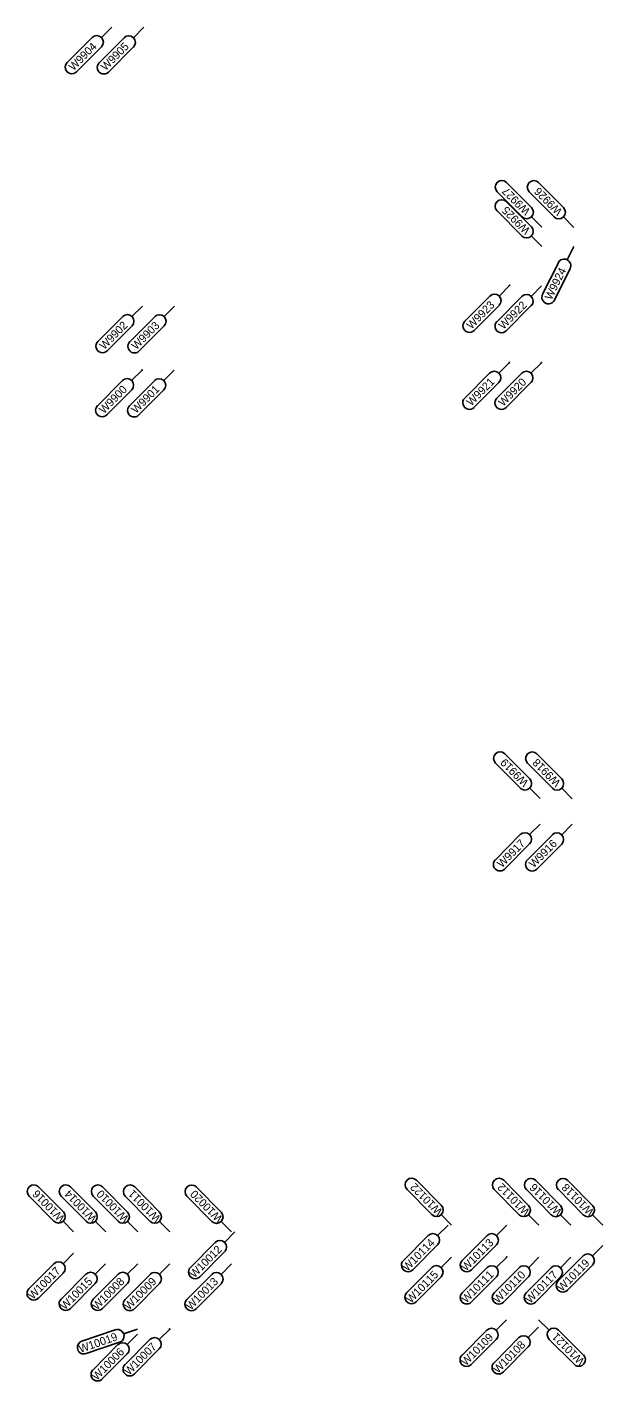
# Model space of a CAD drawing. Extents: x 12479652 to 12487250, y 9842710 to 9846560.
# Drawn here: x 12483661.3 to 12483751.2, y 9844931.3 to 9845142.7 of the extents above; entities that cross this region are included whole.
import ezdxf

# ---------------------------------------------------------------- set-up
doc = ezdxf.new("R2010")
doc.units = 0
doc.layers.add('Default', color=7, linetype='Continuous')
doc.layers.add('TextAlignmentLrg', color=7, linetype='Continuous')

msp = doc.modelspace()

# ---------------------------------------------------------------- linework, layer by layer
at = {"layer": 'Default'}
for p, q in [((12483674.53, 9845142.71), (12483672.91, 9845141.08)), ((12483679.53, 9845142.68), (12483677.91, 9845141.05)), ((12483667.57, 9845137.16), (12483671.46, 9845141.07)), ((12483672.57, 9845137.13), (12483676.46, 9845141.05)), ((12483672.91, 9845139.63), (12483669.02, 9845135.71)), ((12483677.91, 9845139.6), (12483674.02, 9845135.69)), ((12483740.01, 9845114.53), (12483736.12, 9845118.44)), ((12483745.01, 9845114.51), (12483741.12, 9845118.43)), ((12483734.66, 9845116.99), (12483738.55, 9845113.08)), ((12483740, 9845111.53), (12483736.11, 9845115.44)), ((12483739.66, 9845116.98), (12483743.55, 9845113.07)), ((12483734.65, 9845113.99), (12483738.54, 9845110.08)), ((12483741.62, 9845111.45), (12483740, 9845113.08)), ((12483746.62, 9845111.43), (12483745, 9845113.06)), ((12483741.62, 9845108.45), (12483739.99, 9845110.08)), ((12483746.62, 9845108.43), (12483745.59, 9845106.37)), ((12483741.76, 9845100.97), (12483744.22, 9845105.91)), ((12483746.05, 9845104.99), (12483743.6, 9845100.06)), ((12483736.6, 9845102.33), (12483734.98, 9845100.7)), ((12483741.6, 9845102.28), (12483739.98, 9845100.65)), ((12483729.64, 9845096.79), (12483733.53, 9845100.7)), ((12483734.64, 9845096.73), (12483738.52, 9845100.65)), ((12483679.31, 9845099.13), (12483677.69, 9845097.5)), ((12483684.31, 9845099.12), (12483682.69, 9845097.49)), ((12483734.98, 9845099.25), (12483731.09, 9845095.34)), ((12483739.98, 9845099.2), (12483736.09, 9845095.29)), ((12483672.35, 9845093.58), (12483676.24, 9845097.49)), ((12483677.7, 9845096.05), (12483673.81, 9845092.13)), ((12483677.35, 9845093.57), (12483681.24, 9845097.48)), ((12483682.7, 9845096.04), (12483678.81, 9845092.13)), ((12483736.56, 9845090.29), (12483734.94, 9845088.66)), ((12483741.56, 9845090.28), (12483739.94, 9845088.65)), ((12483672.3, 9845083.58), (12483676.19, 9845087.49)), ((12483677.3, 9845083.57), (12483681.19, 9845087.48)), ((12483679.26, 9845089.13), (12483677.64, 9845087.5)), ((12483684.26, 9845089.12), (12483682.64, 9845087.49)), ((12483729.6, 9845084.74), (12483733.49, 9845088.65)), ((12483734.6, 9845084.73), (12483738.49, 9845088.65)), ((12483677.65, 9845086.05), (12483673.76, 9845082.13)), ((12483682.65, 9845086.04), (12483678.76, 9845082.13)), ((12483734.94, 9845087.21), (12483731.05, 9845083.29)), ((12483739.94, 9845087.2), (12483736.05, 9845083.29)), ((12483739.74, 9845025.3), (12483735.85, 9845029.21)), ((12483744.74, 9845025.28), (12483740.85, 9845029.2)), ((12483734.4, 9845027.76), (12483738.29, 9845023.85)), ((12483739.4, 9845027.75), (12483743.29, 9845023.84)), ((12483741.36, 9845022.21), (12483739.74, 9845023.85)), ((12483746.36, 9845022.2), (12483744.74, 9845023.83)), ((12483741.35, 9845018.21), (12483739.73, 9845016.58)), ((12483746.35, 9845018.2), (12483744.73, 9845016.57)), ((12483734.39, 9845012.67), (12483738.28, 9845016.58)), ((12483739.39, 9845012.65), (12483743.28, 9845016.56)), ((12483739.73, 9845015.13), (12483735.84, 9845011.22)), ((12483744.73, 9845015.12), (12483740.84, 9845011.2)), ((12483666.98, 9844957.66), (12483663.11, 9844961.58)), ((12483671.98, 9844957.65), (12483668.11, 9844961.58)), ((12483676.98, 9844957.64), (12483673.11, 9844961.57)), ((12483681.98, 9844957.64), (12483678.11, 9844961.56)), ((12483691.61, 9844957.62), (12483687.73, 9844961.55)), ((12483720.61, 9844961.18), (12483724.49, 9844957.25)), ((12483725.95, 9844958.69), (12483722.07, 9844962.62)), ((12483734.22, 9844961.16), (12483738.09, 9844957.23)), ((12483739.55, 9844958.67), (12483735.68, 9844962.6)), ((12483739.22, 9844961.15), (12483743.09, 9844957.22)), ((12483744.55, 9844958.67), (12483740.68, 9844962.59)), ((12483744.22, 9844961.14), (12483748.09, 9844957.22)), ((12483749.55, 9844958.66), (12483745.68, 9844962.58)), ((12483661.65, 9844960.14), (12483665.52, 9844956.22)), ((12483666.65, 9844960.13), (12483670.52, 9844956.21)), ((12483671.65, 9844960.13), (12483675.52, 9844956.2)), ((12483676.65, 9844960.12), (12483680.53, 9844956.19)), ((12483686.27, 9844960.1), (12483690.15, 9844956.18)), ((12483727.55, 9844955.61), (12483725.94, 9844957.24)), ((12483741.16, 9844955.59), (12483739.54, 9844957.22)), ((12483746.16, 9844955.58), (12483744.54, 9844957.21)), ((12483751.16, 9844955.57), (12483749.54, 9844957.21)), ((12483668.59, 9844954.57), (12483666.97, 9844956.21)), ((12483673.59, 9844954.56), (12483671.97, 9844956.2)), ((12483678.59, 9844954.56), (12483676.97, 9844956.19)), ((12483683.59, 9844954.55), (12483681.98, 9844956.19)), ((12483693.22, 9844954.53), (12483691.6, 9844956.17)), ((12483693.76, 9844954.53), (12483692.14, 9844952.9)), ((12483727, 9844955.61), (12483725.37, 9844953.98)), ((12483736.16, 9844955.6), (12483734.54, 9844953.97)), ((12483686.8, 9844948.99), (12483690.69, 9844952.9)), ((12483720.03, 9844950.06), (12483723.92, 9844953.97)), ((12483725.38, 9844952.53), (12483721.49, 9844948.61)), ((12483729.2, 9844950.05), (12483733.09, 9844953.97)), ((12483734.54, 9844952.52), (12483730.65, 9844948.61)), ((12483751.16, 9844952.43), (12483749.54, 9844950.8)), ((12483668.59, 9844951.2), (12483666.96, 9844949.56)), ((12483692.14, 9844951.45), (12483688.25, 9844947.54)), ((12483727.55, 9844950.61), (12483725.92, 9844948.98)), ((12483736.15, 9844950.59), (12483734.53, 9844948.96)), ((12483741.15, 9844950.59), (12483739.53, 9844948.95)), ((12483744.19, 9844946.88), (12483748.08, 9844950.79)), ((12483746.15, 9844950.58), (12483744.53, 9844948.95)), ((12483661.62, 9844945.65), (12483665.51, 9844949.56)), ((12483666.97, 9844948.11), (12483663.08, 9844944.2)), ((12483666.62, 9844944.02), (12483670.51, 9844947.93)), ((12483671.62, 9844944.01), (12483675.51, 9844947.92)), ((12483673.58, 9844949.56), (12483671.96, 9844947.93)), ((12483676.62, 9844944), (12483680.51, 9844947.91)), ((12483678.58, 9844949.56), (12483676.96, 9844947.93)), ((12483683.58, 9844949.55), (12483681.96, 9844947.92)), ((12483693.21, 9844949.53), (12483691.59, 9844947.9)), ((12483720.58, 9844945.06), (12483724.47, 9844948.97)), ((12483729.19, 9844945.05), (12483733.08, 9844948.96)), ((12483734.19, 9844945.04), (12483738.08, 9844948.95)), ((12483739.19, 9844945.03), (12483743.08, 9844948.94)), ((12483749.54, 9844949.34), (12483745.65, 9844945.43)), ((12483671.97, 9844946.48), (12483668.08, 9844942.57)), ((12483676.97, 9844946.47), (12483673.08, 9844942.56)), ((12483681.97, 9844946.47), (12483678.08, 9844942.55)), ((12483686.25, 9844943.99), (12483690.14, 9844947.9)), ((12483691.59, 9844946.45), (12483687.7, 9844942.54)), ((12483725.93, 9844947.52), (12483722.04, 9844943.61)), ((12483734.54, 9844947.51), (12483730.65, 9844943.6)), ((12483739.54, 9844947.5), (12483735.65, 9844943.59)), ((12483744.54, 9844947.5), (12483740.65, 9844943.58)), ((12483736.14, 9844940.83), (12483734.52, 9844939.2)), ((12483741.14, 9844939.66), (12483739.52, 9844938.03)), ((12483741.14, 9844940.82), (12483742.77, 9844939.2)), ((12483669.87, 9844937.47), (12483675.09, 9844939.26)), ((12483678.57, 9844939.36), (12483676.39, 9844938.62)), ((12483676.61, 9844933.81), (12483680.5, 9844937.72)), ((12483678.57, 9844938.56), (12483676.95, 9844936.93)), ((12483683.57, 9844939.35), (12483681.95, 9844937.72)), ((12483729.18, 9844935.28), (12483733.07, 9844939.19)), ((12483734.52, 9844937.75), (12483730.63, 9844933.83)), ((12483734.18, 9844934.11), (12483738.06, 9844938.03)), ((12483746.69, 9844933.86), (12483742.77, 9844937.75)), ((12483744.22, 9844939.2), (12483748.13, 9844935.31)), ((12483675.75, 9844937.31), (12483670.53, 9844935.53)), ((12483671.61, 9844933.02), (12483675.49, 9844936.93)), ((12483676.95, 9844935.48), (12483673.06, 9844931.57)), ((12483681.95, 9844936.27), (12483678.06, 9844932.36)), ((12483739.52, 9844936.58), (12483735.63, 9844932.67))]:
    msp.add_line(p, q, dxfattribs=at)
for centre, start, end in [((12483672.19, 9845140.35), 315.1702, 135.1702), ((12483677.19, 9845140.32), 315.1702, 135.1702), ((12483668.3, 9845136.44), 135.1702, 315.1702), ((12483673.3, 9845136.41), 135.1702, 315.1702), ((12483735.39, 9845117.72), 44.8253, 224.8253), ((12483740.39, 9845117.7), 44.8253, 224.8253), ((12483735.38, 9845114.72), 44.8253, 224.8253), ((12483739.28, 9845113.8), 224.8253, 44.8253), ((12483744.28, 9845113.79), 224.8253, 44.8253), ((12483739.27, 9845110.8), 224.8253, 44.8253), ((12483745.13, 9845105.45), 333.5553, 153.5553), ((12483734.25, 9845099.98), 315.1702, 135.1702), ((12483739.25, 9845099.92), 315.1702, 135.1702), ((12483742.68, 9845100.51), 153.5553, 333.5553), ((12483676.97, 9845096.77), 315.1702, 135.1702), ((12483681.97, 9845096.76), 315.1702, 135.1702), ((12483730.36, 9845096.06), 135.1702, 315.1702), ((12483735.36, 9845096.01), 135.1702, 315.1702), ((12483673.08, 9845092.86), 135.1702, 315.1702), ((12483678.08, 9845092.85), 135.1702, 315.1702), ((12483676.92, 9845086.77), 315.1702, 135.1702), ((12483681.92, 9845086.76), 315.1702, 135.1702), ((12483734.22, 9845087.93), 315.1702, 135.1702), ((12483739.22, 9845087.92), 315.1702, 135.1702), ((12483673.03, 9845082.86), 135.1702, 315.1702), ((12483678.03, 9845082.85), 135.1702, 315.1702), ((12483730.33, 9845084.02), 135.1702, 315.1702), ((12483735.33, 9845084.01), 135.1702, 315.1702), ((12483735.13, 9845028.49), 44.8253, 224.8253), ((12483740.13, 9845028.47), 44.8253, 224.8253), ((12483739.01, 9845024.57), 224.8253, 44.8253), ((12483744.01, 9845024.56), 224.8253, 44.8253), ((12483739, 9845015.86), 315.1702, 135.1702), ((12483744, 9845015.84), 315.1702, 135.1702), ((12483735.11, 9845011.94), 135.1702, 315.1702), ((12483740.11, 9845011.93), 135.1702, 315.1702), ((12483721.34, 9844961.9), 44.6553, 224.6553), ((12483734.95, 9844961.88), 44.6553, 224.6553), ((12483739.95, 9844961.87), 44.6553, 224.6553), ((12483744.95, 9844961.86), 44.6553, 224.6553), ((12483662.38, 9844960.86), 44.6553, 224.6553), ((12483667.38, 9844960.86), 44.6553, 224.6553), ((12483672.38, 9844960.85), 44.6553, 224.6553), ((12483677.38, 9844960.84), 44.6553, 224.6553), ((12483687, 9844960.83), 44.6553, 224.6553), ((12483725.22, 9844957.97), 224.6553, 44.6553), ((12483738.82, 9844957.95), 224.6553, 44.6553), ((12483743.82, 9844957.94), 224.6553, 44.6553), ((12483748.82, 9844957.94), 224.6553, 44.6553), ((12483666.25, 9844956.94), 224.6553, 44.6553), ((12483671.25, 9844956.93), 224.6553, 44.6553), ((12483676.25, 9844956.92), 224.6553, 44.6553), ((12483681.25, 9844956.92), 224.6553, 44.6553), ((12483690.88, 9844956.9), 224.6553, 44.6553), ((12483724.65, 9844953.25), 315.1702, 135.1702), ((12483733.82, 9844953.24), 315.1702, 135.1702), ((12483691.42, 9844952.18), 315.1702, 135.1702), ((12483720.76, 9844949.34), 135.1702, 315.1702), ((12483729.93, 9844949.33), 135.1702, 315.1702), ((12483748.81, 9844950.07), 315.1702, 135.1702), ((12483666.24, 9844948.84), 315.1702, 135.1702), ((12483671.24, 9844947.21), 315.1702, 135.1702), ((12483676.24, 9844947.2), 315.1702, 135.1702), ((12483681.24, 9844947.19), 315.1702, 135.1702), ((12483687.53, 9844948.26), 135.1702, 315.1702), ((12483690.86, 9844947.18), 315.1702, 135.1702), ((12483725.2, 9844948.25), 315.1702, 135.1702), ((12483733.81, 9844948.23), 315.1702, 135.1702), ((12483738.81, 9844948.23), 315.1702, 135.1702), ((12483743.81, 9844948.22), 315.1702, 135.1702), ((12483744.92, 9844946.16), 135.1702, 315.1702), ((12483662.35, 9844944.92), 135.1702, 315.1702), ((12483667.35, 9844943.29), 135.1702, 315.1702), ((12483672.35, 9844943.29), 135.1702, 315.1702), ((12483677.35, 9844943.28), 135.1702, 315.1702), ((12483686.97, 9844943.26), 135.1702, 315.1702), ((12483721.31, 9844944.34), 135.1702, 315.1702), ((12483729.92, 9844944.32), 135.1702, 315.1702), ((12483734.92, 9844944.31), 135.1702, 315.1702), ((12483739.92, 9844944.31), 135.1702, 315.1702), ((12483733.79, 9844938.47), 315.1702, 135.1702), ((12483743.5, 9844938.48), 45.1702, 225.1702), ((12483670.2, 9844936.5), 108.9045, 288.9045), ((12483675.42, 9844938.28), 288.9045, 108.9045), ((12483681.22, 9844937), 315.1702, 135.1702), ((12483738.79, 9844937.3), 315.1702, 135.1702), ((12483676.22, 9844936.2), 315.1702, 135.1702), ((12483729.9, 9844934.56), 135.1702, 315.1702), ((12483747.41, 9844934.59), 225.1702, 45.1702), ((12483677.33, 9844933.08), 135.1702, 315.1702), ((12483734.9, 9844933.39), 135.1702, 315.1702), ((12483672.33, 9844932.29), 135.1702, 315.1702)]:
    msp.add_arc(centre, 1.03, start, end, dxfattribs=at)
at = {"layer": 'TextAlignmentLrg'}
for centre in [(12483736.6, 9845102.36), (12483736.56, 9845090.29), (12483741.56, 9845090.28), (12483679.26, 9845089.13), (12483736.15, 9844950.59), (12483683.57, 9844939.35)]:
    msp.add_circle(centre, 0.05, dxfattribs=at)

# ---------------------------------------------------------------- texts
at = {"layer": 'Default'}
for s, rotation, p in [('W9905', 45.1702, (12483673.58, 9845135.8)), ('W9904', 45.1702, (12483668.56, 9845135.8)), ('W9927', 134.8253, (12483739.92, 9845114.06)), ('W9926', 134.8253, (12483744.93, 9845114.03)), ('W9925', 134.8253, (12483739.91, 9845111.06)), ('W9924', 63.5553, (12483743.13, 9845099.99)), ('W9923', 45.1702, (12483730.64, 9845095.44)), ('W9922', 45.1702, (12483735.65, 9845095.4)), ('W9902', 45.1702, (12483673.37, 9845092.25)), ('W9903', 45.1702, (12483678.36, 9845092.23)), ('W9921', 45.1702, (12483730.63, 9845083.43)), ('W9920', 45.1702, (12483735.6, 9845083.38)), ('W9900', 45.1702, (12483673.3, 9845082.23)), ('W9901', 45.1702, (12483678.34, 9845082.26)), ('W9919', 134.8253, (12483739.66, 9845024.82)), ('W9918', 134.8253, (12483744.67, 9845024.81)), ('W9917', 45.1702, (12483735.4, 9845011.33)), ('W9916', 45.1702, (12483740.38, 9845011.3)), ('W10016', 134.6553, (12483667.3, 9844956.78)), ('W10014', 134.6553, (12483672.3, 9844956.77)), ('W10010', 134.6553, (12483677.3, 9844956.77)), ('W10011', 134.6553, (12483682.26, 9844956.8)), ('W10020', 134.6553, (12483691.92, 9844956.75)), ('W10122', 134.6553, (12483726.24, 9844957.84)), ('W10112', 134.6553, (12483739.85, 9844957.82)), ('W10116', 134.6553, (12483744.87, 9844957.79)), ('W10118', 134.6553, (12483749.87, 9844957.79)), ('W10012', 45.1702, (12483687.43, 9844947.26)), ('W10114', 45.1702, (12483720.64, 9844948.31)), ('W10113', 45.1702, (12483729.82, 9844948.32)), ('W10119', 45.1702, (12483744.8, 9844945.14)), ('W10017', 45.1702, (12483662.24, 9844943.91)), ('W10115', 45.1702, (12483721.2, 9844943.33)), ('W10111', 45.1702, (12483729.84, 9844943.34)), ('W10110', 45.1702, (12483734.8, 9844943.29)), ('W10117', 45.1702, (12483739.81, 9844943.3)), ('W10015', 45.1702, (12483667.24, 9844942.28)), ('W10008', 45.1702, (12483672.23, 9844942.26)), ('W10009', 45.1702, (12483677.23, 9844942.26)), ('W10013', 45.1702, (12483686.86, 9844942.25)), ('W10019', 18.9045, (12483669.65, 9844935.64)), ('W10109', 45.1702, (12483729.79, 9844933.54)), ('W10108', 45.1702, (12483734.78, 9844932.37)), ('W10121', 135.1702, (12483748.4, 9844934.5)), ('W10006', 45.1702, (12483672.21, 9844931.27)), ('W10007', 45.1702, (12483677.23, 9844932.07))]:
    msp.add_text(s, height=1.25, rotation=rotation, dxfattribs=at).set_placement(p)

doc.saveas('drawing.dxf')
